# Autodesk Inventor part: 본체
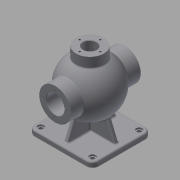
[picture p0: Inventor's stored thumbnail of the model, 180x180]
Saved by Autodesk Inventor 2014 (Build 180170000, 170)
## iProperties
Created: 2015-10
Part Number: 본체
Material: Generic
Document SubType Name: Modeling
Designer: youjin16
Density: 1 g/cm^3
Appearance: Default
Author: youjin16
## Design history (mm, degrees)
sketch "스케치1"
  geometry: L1 (-50.5, -57.5)-(50.5, -57.5); L2 (62.5, -45.5)-(62.5, 45.5); L3 (50.5, 57.5)-(-50.5, 57.5); L4 (-62.5, 45.5)-(-62.5, -45.5); L5 (-62.5, -57.5)-(62.5, 57.5); L6 (62.5, -57.5)-(-62.5, 57.5); C1 r 4 at (-50.5, 45.5); C2 r 4 at (50.5, 45.5); C3 r 4 at (-50.5, -45.5); C4 r 4 at (50.5, -45.5); A1 r 12 centre (-50.5, 45.5) between (-50.5, 57.5) and (-62.5, 45.5); A2 r 12 centre (-50.5, -45.5) between (-62.5, -45.5) and (-50.5, -57.5); A3 r 12 centre (50.5, 45.5) between (62.5, 45.5) and (50.5, 57.5); A4 r 12 centre (50.5, -45.5) between (50.5, -57.5) and (62.5, -45.5); 1 further point
  constraints: 12 end point, 8 centre point, 8 point on circle, 8 point on line, 8 tangent, 4 coincident, 3 equal radius, 2 midpoint, 2 parallel, 1 horizontal, 1 perpendicular
  dimensions: "d0" = 125 distance of L6.end L5.end; "d1" = 115 distance of L5.end L6.start; "d2" = 12 radius of A1; "d3" = 8 diameter of C1; "d4" = 8 diameter of C2; "d5" = 8 diameter of C3; "d6" = 8 diameter of C4
extrude "돌출1" new body sketch "스케치1" distance "d7" = 10; taper "d8" = 0 deg
sketch "스케치2"
  geometry: C1 r 4 at (50.5, -45.5) reference; C2 r 4 at (-50.5, -45.5) reference; C3 r 4 at (50.5, 45.5) reference; C4 r 4 at (-50.5, 45.5) reference; C5 r 6 at (-50.5, 45.5); C6 r 6 at (-50.5, -45.5); C7 r 6 at (50.5, -45.5); C8 r 6 at (50.5, 45.5); A1 r 12 centre (-50.5, -45.5) between (-62.5, -45.5) and (-50.5, -57.5) reference; A2 r 12 centre (50.5, -45.5) between (50.5, -57.5) and (62.5, -45.5) reference; A3 r 12 centre (50.5, 45.5) between (62.5, 45.5) and (50.5, 57.5) reference; A4 r 12 centre (-50.5, 45.5) between (-50.5, 57.5) and (-62.5, 45.5) reference; 1 further point
  constraints: 4 centre point, 4 coincident
  dimensions: "d9" = 12 diameter of C5; "d10" = 12 diameter of C6; "d11" = 12 diameter of C7; "d12" = 12 diameter of C8
extrude "돌출2" cut sketch "스케치2" distance "d13" = 3; taper "d14" = 0 deg
sketch "스케치3"
  geometry: L1 (0, 138)-(0, 32); A1 r 53 centre (0, 85) between (0, 138) and (0, 32); A2 r 53 centre (0, 85) between (0, 32) and (0, 138); 2 further points
  constraints: 4 point on circle, 2 centre point, 2 end point, 2 vertical alignment, 1 midpoint, 1 vertical
  dimensions: "d15" = 106 diameter of A1; "d16" = 85 distance of point (0, 0) A1.centre
revolve "회전1" sketch "스케치3" stored, may be unused: angle "d17" = 90 deg
node "작업 평면1"
sketch "스케치4"
  geometry: C1 r 31 at (0, 85); 1 further point
  constraints: 1 centre point, 1 vertical alignment
  dimensions: "d19" = 62 diameter of C1; "d20" = 85 distance of point (0, 0) C1.centre
extrude "돌출3" join sketch "스케치4" distance "d21" = 136; taper "d22" = 0 deg
node "작업 평면2"
sketch "스케치5"
  geometry: C1 r 27 at (0, 0); 1 further point
  constraints: 1 centre point, 1 coincident
  dimensions: "d24" = 54 diameter of C1
extrude "돌출4" join sketch "스케치5" stored distance "d25" = 136; taper "d26" = 0 deg
sketch "스케치8"
  geometry: L1 (-27, 130.607)-(27, 130.607) reference; L2 (0, 128)-(0, 42); C1 r 31 at (0, 85) reference; C2 r 31 at (0, 85) reference; A1 r 43 centre (0, 85) between (0, 128) and (0, 42); A2 r 43 centre (0, 85) between (0, 42) and (0, 128); 2 further points
  constraints: 4 point on circle, 2 centre point, 2 end point, 2 vertical alignment, 1 coincident, 1 midpoint
  dimensions: "d39" = 86 diameter of A1
revolve "회전2" sketch "스케치8" stored, may be unused: angle "d40" = 90 deg
sketch "스케치9"
  geometry: C1 r 31 at (0, 0) reference; C2 r 17.5 at (0, 0); 1 further point
  constraints: 1 centre point, 1 coincident
  dimensions: "d41" = 35 diameter of C2
extrude "돌출7" cut sketch "스케치9" stored distance "d42" = 8; taper "d43" = 0 deg
sketch "스케치10"
  geometry: C1 r 31 at (0, 0) reference; C2 r 17.5 at (0, 0); 1 further point
  constraints: 1 centre point, 1 coincident
  dimensions: "d44" = 35 diameter of C2
extrude "돌출8" cut sketch "스케치10" distance "d45" = 16; taper "d46" = 0 deg
sketch "스케치11"
  geometry: C1 r 17.5 at (0, 0) reference; C2 r 18.5 at (0, 0); 1 further point
  constraints: 1 centre point, 1 coincident
  dimensions: "d47" = 37 diameter of C2
extrude "돌출9" cut sketch "스케치11" distance "d48" = 1.75; taper "d49" = 0 deg
sketch "스케치12"
  geometry: C1 r 18.5 at (0, 0) reference; C2 r 17.5 at (0, 0); 1 further point
  constraints: 1 centre point, 1 coincident
  dimensions: "d50" = 35 diameter of C2
extrude "돌출10" cut sketch "스케치12" stored distance "d51" = 1.75; taper "d52" = 0 deg
sketch "스케치13"
  geometry: C1 r 27 at (0, 0) reference; C2 r 13 at (0, 0)
  constraints: 1 centre point, 1 coincident
  dimensions: "d53" = 26 diameter of C2
extrude "돌출11" cut sketch "스케치13" stored distance "d54" = 1.75; taper "d55" = 0 deg
sketch "스케치14"
  geometry: C1 r 13 at (0, 0) reference; C2 r 27 at (0, 0) reference; A1 r 20 centre (0, 0) between (-20, 0) and (0, 20); 2 further points
  constraints: 4 point on circle, 2 horizontal alignment, 2 vertical alignment, 1 centre point, 1 coincident
  dimensions: "d56" = 40 diameter of A1
hole "구멍1" sketch "스케치14" at (-20, 0), (0, 20), (20, 0), (0, -20) diameter "d57" = 3.242; stored, may be unused: countersink angle "d61" = 90 deg, drill point angle "d63" = 0 deg; dims "d58" = 9, "d59" = 35, "d60" = 16, "d62" = 11
sketch "스케치15"
  geometry: C1 r 17.5 at (0, 0) reference; C2 r 31 at (0, 0) reference; A1 r 22.5 centre (0, 0) between (-22.5, 0) and (0, 22.5); 3 further points
  constraints: 4 point on circle, 2 horizontal alignment, 2 vertical alignment, 1 centre point, 1 coincident
  dimensions: "d64" = 45 diameter of A1
hole "구멍2" sketch "스케치15" at (-22.5, 0), (0, 22.5), (22.5, 0), (0, -22.5) diameter "d65" = 3.242; stored, may be unused: countersink angle "d69" = 90 deg, drill point angle "d71" = 0 deg; dims "d66" = 12, "d67" = 35, "d68" = 16, "d70" = 15
sketch "스케치16"
  geometry: C1 r 17.5 at (0, 0) reference; C2 r 31 at (0, 0) reference; A1 r 24 centre (0, 0) between (0, 24) and (24, 0); 3 further points
  constraints: 4 point on circle, 2 horizontal alignment, 2 vertical alignment, 1 centre point, 1 coincident
  dimensions: "d72" = 48 diameter of A1
hole "구멍3" sketch "스케치16" at (0, 24), (24, 0), (-24, 0), (0, -24) diameter "d73" = 3.242; stored, may be unused: countersink angle "d77" = 90 deg, drill point angle "d79" = 0 deg; dims "d74" = 16, "d75" = 35, "d76" = 16, "d78" = 19
node "작업 평면3"
sketch "스케치17"
  geometry: L1 (-27, 150)-(27, 150) reference; 3 further points
  constraints: 1 midpoint, 1 vertical alignment, 1 other
  dimensions: "d81" = 10 vertical distance of L1.end point (0, 140)
feature "엠보싱1" dims "d82" = 0.5, "d83" = 0
sketch "스케치24"
  geometry: L1 (-4, -4)-(4, -4); L2 (4, -4)-(4, 4); L3 (4, 4)-(-4, 4); L4 (-4, 4)-(-4, -4); L5 (-4, -4)-(4, 4); L6 (4, -4)-(-4, 4); 3 further points
  constraints: 12 end point, 3 midpoint, 2 parallel, 1 coincident, 1 horizontal, 1 perpendicular
  dimensions: "d84" = 8 distance of L3.end L2.end; "d85" = 8 distance of L2.end L1.end
extrude "돌출12" join sketch "스케치24" stored distance "d86" = 50; taper "d87" = 0 deg
sketch "스케치25"
  geometry: L1 (4, 32.303)-(4, 32.303) reference; L2 (-4, 32.303)-(-4, 32.303) reference; L3 (-27, 130.607)-(27, 130.607) reference; L4 (-50.5, 10)-(50.5, 10) reference; L5 (-50.5, 10)-(-62.5, 10) reference; L6 (62.5, 10)-(50.5, 10) reference; L7 (-37.379, 47.426)-(-52.5, 10); L8 (37.379, 47.426)-(52.5, 10); C1 r 31 at (0, 85) reference; C2 r 31 at (0, 85) reference; A1 r 52.849 centre (0, 85) between (-4, 32.303) and (4, 32.303) reference; A2 r 52.849 centre (0, 85) between (-4, 32.303) and (4, 32.303) reference; A3 r 53 centre (0, 85) between (-27, 130.607) and (27, 130.607) reference; 1 further point
  constraints: 4 end point, 2 point on circle, 2 point on line
  dimensions: "d88" = 112 deg angle of L5 L7; "d89" = 10 distance of L5.end L7.end; "d90" = 112 deg angle of L6 L8; "d91" = 10 distance of L6.start L8.end
  node "투영된 루프15"
feature "리브1" dims "d92" = 1, "d93" = 8, "d94" = 0, "d95" = 0, "d96" = 1, "d97" = 1
feature "리브2" dims "d98" = 1, "d99" = 8, "d100" = 0, "d101" = 0, "d102" = 1, "d103" = 1
sketch "스케치26"
  geometry: L1 (45.5, 10)-(-45.5, 10) reference; L2 (39.5, 10)-(51.5, 10) reference; L3 (-51.5, 10)-(-39.5, 10) reference; L4 (-45.5, 10)-(-57.5, 10) reference; L5 (57.5, 10)-(45.5, 10) reference; L6 (-47.5, 10)-(-33.719, 44.109); L7 (33.719, 44.109)-(47.5, 10); A1 r 53 centre (0, 85) between (42.988, 116) and (42.988, 54) reference; 1 further point
  constraints: 4 end point, 2 point on circle, 2 point on line
  dimensions: "d104" = 112 deg angle of L4 L6; "d105" = 112 deg angle of L5 L7; "d106" = 10 distance of L5.start L7.end; "d107" = 10 distance of L4.end L6.start
feature "리브3" dims "d108" = 1, "d109" = 8, "d110" = 0, "d111" = 0, "d112" = 1, "d113" = 1
feature "리브4" dims "d114" = 1, "d115" = 8, "d116" = 0, "d117" = 0, "d118" = 1, "d119" = 1
fillet "모깎기1" dims "d120" = 3
chamfer "모따기1" distance "d121" = 1; stored, may be unused: second distance "d122" = 2, angle "d123" = 45 deg
chamfer "모따기2" distance "d124" = 1; stored, may be unused: second distance "d125" = 2, angle "d126" = 45 deg
chamfer "모따기3" distance "d127" = 1; stored, may be unused: second distance "d128" = 2, angle "d129" = 45 deg
node "솔리드1"
node "투영된 루프10"
other parameters: "d18" = -68, "d80" = -27.5
